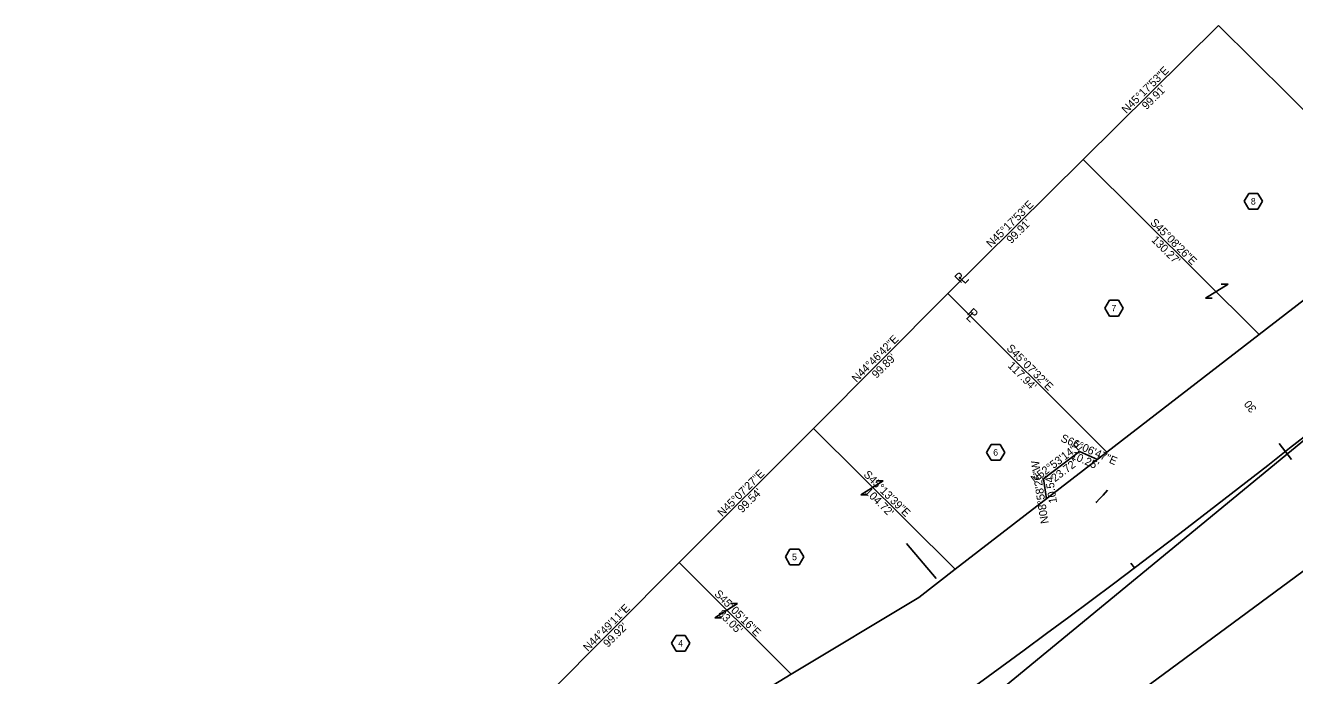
# Model space of a CAD drawing. Extents: x 1145508 to 2262867, y -3126236 to 2021677.
# Drawn here: x 1146074 to 1146740, y 2016667 to 2017008 of the extents above; entities that cross this region are included whole.
import ezdxf

# ---------------------------------------------------------------- set-up
doc = ezdxf.new("R2010")
doc.units = 0
for name, color, linetype in [('DSN_RDWY_Alignment', 7, 'Continuous'), ('DSN_RDWY_Alignment Annotation', 7, 'Continuous'), ('DSN_RDWY_Const Limits', 7, 'Continuous'), ('DSN_ROW_Annotation', 7, 'Continuous'), ('DSN_ROW_Esmnt', 7, 'Continuous'), ('DSN_ROW_Prop-Line', 7, 'Continuous'), ('DSN_ROW_Prop-Line-Annotation', 7, 'Continuous'), ('E_Const Align', 7, 'Continuous'), ('EX_ROW', 7, 'Continuous'), ('EX_SIGN', 7, 'Continuous'), ('EX_SUBDIV_ANNOT', 7, 'Continuous')]:
    doc.layers.add(name, color=color, linetype=linetype)

msp = doc.modelspace()

# ---------------------------------------------------------------- linework, layer by layer
at = {"layer": 'DSN_RDWY_Alignment'}
msp.add_line((1146478.89, 2016571.64), (1146840, 2016868.61), dxfattribs=at)
at = {"layer": 'DSN_RDWY_Alignment Annotation'}
for p, q in [((1146732.18, 2016788.89), (1146738.73, 2016780.53)), ((1146654.43, 2016726.07), (1146656.24, 2016723.68))]:
    msp.add_line(p, q, dxfattribs=at)
at = {"layer": 'DSN_RDWY_Const Limits'}
msp.add_lwpolyline([(1146636.09, 2016757.95), (1146636.35, 2016758.22), (1146637.7, 2016759.65), (1146638.03, 2016760), (1146639.81, 2016761.88), (1146642.04, 2016764.49)], dxfattribs=at)
at = {"layer": 'DSN_ROW_Esmnt'}
for p, q in [((1146608.55, 2016770.37), (1146627.46, 2016784.68)), ((1146627.46, 2016784.68), (1146636.84, 2016780.53)), ((1146610.19, 2016759.96), (1146608.55, 2016770.37))]:
    msp.add_line(p, q, dxfattribs=at)
at = {"layer": 'DSN_ROW_Prop-Line'}
for p, q in [((1146629.3, 2016937.91), (1146700.32, 2017008.19)), ((1146558.29, 2016867.62), (1146629.3, 2016937.91)), ((1146629.3, 2016937.91), (1146721.65, 2016846.02)), ((1146487.93, 2016796.72), (1146558.29, 2016867.62)), ((1146558.29, 2016867.62), (1146641.86, 2016784.41)), ((1146417.39, 2016726.49), (1146487.93, 2016796.72)), ((1146487.93, 2016796.72), (1146562.27, 2016722.96)), ((1146346.96, 2016655.61), (1146417.39, 2016726.49)), ((1146417.39, 2016726.49), (1146476.21, 2016667.86))]:
    msp.add_line(p, q, dxfattribs=at)
at = {"layer": 'DSN_ROW_Prop-Line-Annotation'}
for p, q in [((1146705.38, 2016872.55), (1146693.52, 2016865.16)), ((1146701.83, 2016872.55), (1146705.38, 2016872.55)), ((1146693.52, 2016865.16), (1146697.07, 2016865.16)), ((1146524.5, 2016769.41), (1146512.65, 2016762.03)), ((1146520.96, 2016769.41), (1146524.5, 2016769.41)), ((1146512.65, 2016762.03), (1146516.19, 2016762.03)), ((1146447.95, 2016704.92), (1146436.09, 2016697.53)), ((1146444.4, 2016704.92), (1146447.95, 2016704.92)), ((1146436.09, 2016697.53), (1146439.64, 2016697.53))]:
    msp.add_line(p, q, dxfattribs=at)
at = {"layer": 'E_Const Align'}
msp.add_arc((1143200.69, 2021293.93), 5729.58, 300.103113, 309.43332, dxfattribs=at)
msp.add_arc((1143200.69, 2021293.93), 5729.58, 300.103113, 309.43332, dxfattribs=at)
at = {"layer": 'EX_ROW'}
for p, q in [((1146700.32, 2017008.19), (1146794.02, 2016915.09)), ((1146721.65, 2016846.02), (1146793.37, 2016901.4)), ((1146641.86, 2016784.41), (1146721.65, 2016846.02)), ((1146562.27, 2016722.96), (1146641.86, 2016784.41)), ((1146613.11, 2016624.88), (1146786.28, 2016752.61)), ((1146543.14, 2016708.19), (1146562.27, 2016722.96)), ((1146476.21, 2016667.86), (1146543.14, 2016708.19)), ((1146387.93, 2016614.66), (1146476.21, 2016667.86))]:
    msp.add_line(p, q, dxfattribs=at)
at = {"layer": 'EX_SIGN'}
msp.add_line((1146536.59, 2016736.48), (1146552.22, 2016718.08), dxfattribs=at)
at = {"layer": 'EX_SUBDIV_ANNOT'}
for p, q in [((1146713.84, 2016915.92), (1146716.24, 2016920.08)), ((1146716.24, 2016911.76), (1146713.84, 2016915.92)), ((1146716.24, 2016920.08), (1146721.04, 2016920.08)), ((1146721.04, 2016920.08), (1146723.44, 2016915.92)), ((1146723.44, 2016915.92), (1146721.05, 2016911.76)), ((1146721.05, 2016911.76), (1146716.24, 2016911.76)), ((1146640.71, 2016859.88), (1146643.11, 2016864.04)), ((1146643.11, 2016864.04), (1146647.91, 2016864.04)), ((1146647.91, 2016864.04), (1146650.31, 2016859.88)), ((1146643.11, 2016855.72), (1146640.71, 2016859.88)), ((1146647.91, 2016855.72), (1146643.11, 2016855.72)), ((1146650.31, 2016859.88), (1146647.91, 2016855.72)), ((1146578.66, 2016784.27), (1146581.06, 2016788.42)), ((1146581.06, 2016788.42), (1146585.86, 2016788.42)), ((1146585.86, 2016788.42), (1146588.26, 2016784.27)), ((1146581.06, 2016780.11), (1146578.66, 2016784.27)), ((1146588.26, 2016784.27), (1146585.87, 2016780.11)), ((1146585.87, 2016780.11), (1146581.06, 2016780.11)), ((1146473.15, 2016729.4), (1146475.55, 2016733.56)), ((1146475.55, 2016725.24), (1146473.15, 2016729.4)), ((1146475.55, 2016733.56), (1146480.35, 2016733.56)), ((1146480.35, 2016733.56), (1146482.75, 2016729.4)), ((1146482.75, 2016729.4), (1146480.36, 2016725.24)), ((1146480.36, 2016725.24), (1146475.55, 2016725.24)), ((1146413.41, 2016684.12), (1146415.81, 2016688.28)), ((1146415.81, 2016688.28), (1146420.61, 2016688.28)), ((1146420.61, 2016688.28), (1146423.01, 2016684.12)), ((1146415.81, 2016679.96), (1146413.41, 2016684.12)), ((1146423.01, 2016684.12), (1146420.61, 2016679.96)), ((1146420.61, 2016679.96), (1146415.81, 2016679.96))]:
    msp.add_line(p, q, dxfattribs=at)

# ---------------------------------------------------------------- texts
at = {"layer": 'DSN_RDWY_Alignment Annotation'}
msp.add_text('30', height=4.2, rotation=128.09277, dxfattribs=at).set_placement((1146720.58, 2016807.09))
at = {"layer": 'DSN_ROW_Annotation'}
for s, rotation, p in [('N45°17\'53"E', 44.7019, (1146652.05, 2016961.69)), ("99.91'", 44.7019, (1146662.6, 2016963.69)), ('N45°17\'53"E', 44.7019, (1146581.04, 2016891.41)), ("99.91'", 44.7019, (1146591.59, 2016893.41)), ('S45°08\'26"E', 315.14065, (1146664.23, 2016904.42)), ("130.27'", 315.14065, (1146664.89, 2016895.3)), ('N44°46\'42"E', 45.22162, (1146510.45, 2016820.7)), ('S45°07\'32"E', 315.12542, (1146588.83, 2016838.48)), ("99.89'", 45.22162, (1146520.99, 2016822.79)), ("117.94'", 315.12542, (1146589.49, 2016829.36)), ('N52°53\'14"E', 37.11277, (1146603.86, 2016767.95)), ('S66°06\'47"E', 336.11303, (1146617.19, 2016790.22)), ("23.72'", 37.11277, (1146614.58, 2016768.54)), ("10.25'", 336.11303, (1146622.63, 2016781.25)), ('N45°07\'27"E', 44.87578, (1146439.94, 2016750.21)), ('S45°13\'39"E', 315.22763, (1146513.83, 2016772.29)), ('N08°58\'26"W', 98.97392, (1146611.3, 2016747.18)), ("10.54'", 98.97392, (1146615.68, 2016757.91)), ("99.54'", 44.87578, (1146450.48, 2016752.24)), ("104.72'", 315.22763, (1146514.51, 2016763.16)), ('S45°05\'16"E', 315.08784, (1146435.56, 2016709.65)), ('N44°49\'11"E', 45.1803, (1146369.51, 2016679.59)), ("83.05'", 315.08784, (1146437.43, 2016699.32)), ("99.92'", 45.1803, (1146380.05, 2016681.68))]:
    msp.add_text(s, height=4.2, rotation=rotation, dxfattribs=at).set_placement(p)
at = {"layer": 'DSN_ROW_Esmnt'}
for p in [(1146626.46, 2016783.68), (1146607.55, 2016769.37)]:
    msp.add_text('b', height=2, dxfattribs=at).set_placement(p)
at = {"layer": 'DSN_ROW_Prop-Line-Annotation'}
for s, rotation, p in [('P', 46.7793, (1146564.97, 2016872.67)), ('L', 46.7793, (1146567.17, 2016872.21)), ('L', 315.67685, (1146567.57, 2016854.68)), ('P', 315.67685, (1146568.08, 2016856.87))]:
    msp.add_text(s, height=5, rotation=rotation, dxfattribs=at).set_placement(p)
at = {"layer": 'EX_SUBDIV_ANNOT'}
for s, p in [('8', (1146717.34, 2016914.21)), ('7', (1146644.2, 2016858.17)), ('6', (1146582.16, 2016782.56)), ('5', (1146476.65, 2016727.69)), ('4', (1146416.9, 2016682.41))]:
    msp.add_text(s, height=3.42, dxfattribs=at).set_placement(p)

doc.saveas('drawing.dxf')
